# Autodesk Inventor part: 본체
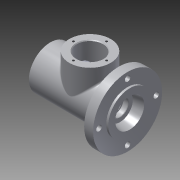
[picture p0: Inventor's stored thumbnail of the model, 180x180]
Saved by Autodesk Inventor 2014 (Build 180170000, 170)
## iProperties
Created: 2016-08
Part Number: 본체
Material: Aluminum 6061
Document SubType Name: Modeling
Designer: user
Density: 2.71 g/cm^3
Appearance: Aluminum - Flat
Mass: 763.571 g
Surface Area: 633.97 cm^2
Volume: 281.761 cm^3
Author: user
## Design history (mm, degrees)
sketch "Sketch1"
  geometry: L1 (-57.5, 0)-(57.5, 0); L2 (57.5, 0)-(57.5, -31); L3 (57.5, -31)-(54.5, -31); L4 (54.5, -31)-(54.5, -50); L5 (54.5, -50)-(41.5, -50); L6 (41.5, -50)-(41.5, -31); L7 (41.5, -31)-(-57.5, -31); L8 (-57.5, -31)-(-57.5, 0); 2 further points
  constraints: 16 end point, 4 parallel, 2 perpendicular, 1 coincident, 1 collinear, 1 horizontal, 1 midpoint
  dimensions: "d0" = 115 distance of L1.start L1.end; "d1" = 62 diameter of L7 L1; "d2" = 100 diameter of L5 L1; "d3" = 62 diameter of L3 L1; "d4" = 3 distance between parallel lines of L2 L4; "d5" = 13 distance between parallel lines of L4 L6
revolve "Revolution1" sketch "Sketch1" stored, may be unused: angle "d6" = 90 deg
hole "Hole1" diameter "d9" = 40.376; stored, may be unused: countersink angle "d13" = 90 deg, drill point angle "d15" = 0 deg; dims "d10" = 9, "d11" = 4, "d12" = 2, "d14" = 9, "d16" = 10, "d17" = 10
sketch "Sketch2"
  geometry: C1 r 20.188 at (0, 0) reference; C2 r 24 at (0, 0)
  constraints: 1 centre point, 1 coincident
  dimensions: "d18" = 48 diameter of C2
extrude "Extrusion1" cut sketch "Sketch2" distance "d19" = 3; taper "d20" = 0 deg
sketch "Sketch3"
  geometry: C1 r 20.188 at (0, 0) reference; C2 r 20 at (0, 0)
  constraints: 1 centre point, 1 coincident
  dimensions: "d21" = 40 diameter of C2
extrude "Extrusion2" cut sketch "Sketch3" distance "d22" = 9; taper "d23" = 0 deg
sketch "Sketch4"
  geometry: C1 r 20 at (0, 0) reference; C2 r 17.5 at (0, 0)
  constraints: 1 centre point, 1 coincident
  dimensions: "d24" = 35 diameter of C2
extrude "Extrusion3" cut sketch "Sketch4" distance "d25" = 5; taper "d26" = 0 deg
sketch "Sketch6"
  geometry: L1 (0, 62.672)-(0, -65.545); L2 (-65.414, 0)-(73.771, 0); C1 r 50 at (0, 0) reference; C2 r 4 at (0, 41.5); C3 r 4 at (41.5, 0); C4 r 4 at (0, -41.5); C5 r 4 at (-41.5, 0); A1 r 41.5 centre (0, 0) between (0, 41.5) and (41.5, 0)
  constraints: 5 centre point, 4 end point, 4 point on circle, 4 point on line, 1 coincident, 1 perpendicular, 1 vertical
  dimensions: "d30" = 83 diameter of A1; "d31" = 8 diameter of C2; "d32" = 8 diameter of C3; "d33" = 8 diameter of C4; "d34" = 8 diameter of C5
extrude "Extrusion5" cut sketch "Sketch6" stored distance "d35" = 1.75; taper "d36" = 0 deg
sketch "Sketch7"
  geometry: C1 r 31 at (0, 0) reference; C2 r 21 at (0, 0)
  constraints: 1 centre point, 1 coincident
  dimensions: "d37" = 42 diameter of C2
extrude "Extrusion6" cut sketch "Sketch7" distance "d38" = 14; taper "d39" = -10 deg
sketch "Sketch8"
  geometry: C1 r 18.531 at (0, 0) reference; C2 r 12.5 at (0, 0)
  constraints: 1 centre point, 1 coincident
  dimensions: "d40" = 25 diameter of C2
extrude "Extrusion7" cut sketch "Sketch8" distance "d41" = 0.7; taper "d42" = -30 deg
sketch "Sketch9"
  geometry: C1 r 12.096 at (0, 0) reference; C2 r 12.5 at (0, 0)
  constraints: 1 centre point, 1 coincident
  dimensions: "d43" = 25 diameter of C2
extrude "Extrusion8" cut sketch "Sketch9" distance "d44" = 6.6; taper "d45" = 0 deg
sketch "Sketch10"
  geometry: C1 r 12.096 at (0, 0) reference; C2 r 10 at (0, 0)
  constraints: 1 centre point, 1 coincident
  dimensions: "d46" = 20 diameter of C2
extrude "Extrusion9" cut sketch "Sketch10" distance "d47" = 2.7; taper "d48" = 0 deg
sketch "Sketch12"
  geometry: C1 r 17.5 at (0, 0) reference; C2 r 18.5 at (0, 0)
  constraints: 1 centre point, 1 coincident
  dimensions: "d52" = 37 diameter of C2
extrude "Extrusion11" cut sketch "Sketch12" distance "d53" = 1.75; taper "d54" = 0 deg
sketch "Sketch13"
  geometry: C1 r 18.5 at (0, 0) reference; C2 r 17.5 at (0, 0)
  constraints: 1 centre point, 1 coincident
  dimensions: "d55" = 35 diameter of C2
extrude "Extrusion12" cut sketch "Sketch13" distance "d56" = 11; taper "d57" = 0 deg
sketch "Sketch14"
  geometry: C1 r 17.5 at (0, 0) reference; C2 r 26 at (0, 0)
  constraints: 1 centre point, 1 coincident
  dimensions: "d58" = 52 diameter of C2
extrude "Extrusion13" cut sketch "Sketch14" distance "d59" = 38; taper "d60" = 0 deg
sketch "Sketch15"
  geometry: C1 r 26 at (0, 0) reference; C2 r 17.5 at (0, 0)
  constraints: 1 centre point, 1 coincident
  dimensions: "d61" = 35 diameter of C2
extrude "Extrusion14" cut sketch "Sketch15" distance "d62" = 11; taper "d63" = 0 deg
sketch "Sketch16"
  geometry: C1 r 17.5 at (0, 0) reference; C2 r 16.5 at (0, 0)
  constraints: 1 centre point, 1 coincident
  dimensions: "d64" = 33 diameter of C2
extrude "Extrusion15" cut sketch "Sketch16" stored distance "d65" = 5; taper "d66" = 0 deg
fillet "Fillet2" dims "d68" = 3
fillet "Fillet3" dims "d69" = 0.3
fillet "Fillet4" dims "d70" = 0.3
fillet "Fillet6" dims "d72" = 3
workplane "Work Plane1"
sketch "Sketch17"
  geometry: C1 r 30 at (0, 0); 1 further point
  constraints: 1 centre point, 1 coincident
  dimensions: "d74" = 60 diameter of C1
extrude "Extrusion16" join sketch "Sketch17" stored distance "d75" = 5; taper "d76" = 0 deg
sketch "Sketch18"
  geometry: C1 r 30 at (0, 0) reference; C2 r 19 at (0, 0)
  constraints: 1 centre point, 1 coincident
  dimensions: "d77" = 38 diameter of C2
extrude "Extrusion17" cut sketch "Sketch18" stored distance "d78" = 5; taper "d79" = 0 deg
sketch "Sketch19"
  geometry: L1 (0, 71.001)-(0, -75.54); L2 (-75.053, 0)-(95.154, 0); C1 r 30 at (0, 0) reference; A1 r 24 centre (0, 0) between (0, 24) and (24, 0); 2 further points
  constraints: 4 end point, 4 point on circle, 4 point on line, 1 centre point, 1 coincident, 1 perpendicular, 1 vertical
  dimensions: "d80" = 48 diameter of A1
hole "Hole2" sketch "Sketch19" at (0, 24), (24, 0), (-24, 0), (0, -24) diameter "d81" = 3.242; stored, may be unused: countersink angle "d85" = 90 deg, drill point angle "d87" = 118 deg; dims "d82" = 8, "d83" = 4, "d84" = 2, "d86" = 10
workplane "Work Plane2"
sketch "Sketch20"
  geometry: L1 (-30, 49)-(30, 49) reference; L2 (57.5, -31)-(57.5, 31) reference; 2 further points
  constraints: 1 other
  dimensions: "d89" = 10 distance from line of point (1.5, 39) L1; "d90" = 56 distance from line of point (1.5, 39) L2
emboss "Emboss1" sketch "Sketch20" dims "d0" = 115, "d1" = 62, "d2" = 100, "d3" = 62, "d4" = 3, "d5" = 13, "d91" = 0.5, "d92" = 0
chamfer "Chamfer1" distance "d93" = 1; stored, may be unused: second distance "d94" = 2, angle "d95" = 45 deg
fillet "Fillet7" dims "d96" = 3
body "Solid1"
other parameters: "d73" = 49
